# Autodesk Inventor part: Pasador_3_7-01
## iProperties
Created: 2008-01
Part Number: Pasador_3_7-01
Material: Default
Document SubType Name: Modeling
Designer: eruiz-tagle
Mass: 0.351876 g
Surface Area: 4.46973 cm^2
Volume: 0.351876 cm^3
Density: 1 g/cm^3
Author: eruiz-tagle
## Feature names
1. Derived Body1 [Tagging]
